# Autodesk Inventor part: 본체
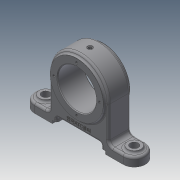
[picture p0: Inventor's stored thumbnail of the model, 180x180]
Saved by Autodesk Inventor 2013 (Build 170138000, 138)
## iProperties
Created: 2019-05
Part Number: 본체
Material: Generic
Document SubType Name: Modeling
Designer: user
Density: 1 g/cm^3
Mass: 168.533 g
Surface Area: 318.665 cm^2
Volume: 168.533 cm^3
Author: user
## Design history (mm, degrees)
sketch "스케치1"
  geometry: L1 (40, 0)-(40, -60); L2 (-40, 0)-(-40, -60); L3 (-40, -60)-(40, -60); A1 r 40 centre (0, 0) between (40, 0) and (-40, 0); 1 further point
  constraints: 6 end point, 2 point on circle, 2 tangent, 1 centre point, 1 coincident, 1 parallel
  dimensions: "d0" = 80 diameter of A1; "d2" = 60 distance of L1.start L1.end; "d3" = 60 distance of L2.start L2.end
extrude "돌출1" new body sketch "스케치1" stored distance "d4" = 30; taper "d5" = 0 deg
node "작업 평면1"
sketch "스케치2"
  geometry: L1 (60, -15)-(-60, -15); L2 (-60, 15)-(60, 15); L3 (-60, -15)-(60, -15); L4 (60, -15)-(60, 15); L5 (60, 15)-(-60, 15); L6 (-60, 15)-(-60, -15); L7 (-60, -15)-(60, 15); L8 (60, -15)-(-60, 15); L9 (-60, 15)-(-60, -15); L10 (60, 15)-(60, -15); L11 (0, 15)-(0, -15); C1 r 15 at (-60, 0); 2 further points
  constraints: 22 end point, 5 equal length, 5 midpoint, 2 horizontal, 1 centre point, 1 perpendicular, 1 symmetric about line, 1 vertical alignment, 3 other
  dimensions: "d9" = 120 distance of L2.start L2.end; "d10" = 30 distance of L1.start L2.end
extrude "돌출2" join sketch "스케치2" distance "d11" = 12; taper "d12" = 0 deg
sketch "스케치3"
  geometry: C1 r 36 at (0, 0); A1 r 40 centre (0, 0) between (40, 0) and (-40, 0) reference
  constraints: 1 centre point, 1 coincident
  dimensions: "d13" = 72 diameter of C1
extrude "돌출3" join sketch "스케치3" distance "d14" = 3; taper "d15" = 0 deg
sketch "스케치4"
  geometry: C1 r 36 at (0, 0); A1 r 40 centre (0, 0) between (40, 0) and (-40, 0) reference
  constraints: 1 centre point, 1 coincident
  dimensions: "d16" = 72 diameter of C1
extrude "돌출4" join sketch "스케치4" distance "d17" = 3; taper "d18" = 0 deg
sketch "스케치5"
  geometry: C1 r 36 at (0, 0) reference; C2 r 26 at (0, 0)
  constraints: 1 centre point, 1 coincident
  dimensions: "d19" = 52 diameter of C2
extrude "돌출5" cut sketch "스케치5" stored distance "d20" = 3; taper "d21" = 0 deg
sketch "스케치6"
  geometry: L1 (-40, 0)-(-40, -48) reference; L2 (-60, -60)-(60, -60) reference; L3 (0, -60)-(-36, -60); L4 (-36, -60)-(-36, -56); L5 (-36, -56)-(-30, -56); L6 (-30, -56)-(-30, -50); L7 (-30, -50)-(0, -50); L8 (0, -60)-(0, -50); L9 (30, -50)-(0, -50); L10 (30, -56)-(30, -50); L11 (36, -56)-(30, -56); L12 (36, -60)-(36, -56); L13 (0, -60)-(36, -60)
  constraints: 22 end point, 4 symmetric about line, 3 perpendicular, 1 midpoint, 1 parallel, 1 point on line
  dimensions: "d23" = 36 distance of L3.start L3.end; "d24" = 4 distance of L3.end L4.end; "d26" = 6 distance of L4.end L5.end; "d27" = 6 distance of L5.end L6.end; "d28" = 30 distance of L6.end L7.end
extrude "돌출6" cut sketch "스케치6" stored distance "d29" = 3; taper "d30" = 0 deg
chamfer "모따기1" distance "d31" = 1; stored, may be unused: second distance "d32" = 2, angle "d33" = 45 deg
sketch "스케치8"
  geometry: L1 (0, 27)-(0, 26); C1 r 36 at (0, 0) reference; C2 r 1.5 at (0, 26); 2 further points
  constraints: 3 vertical alignment, 2 end point, 1 centre point, 1 coincident, 1 vertical, 2 other
  dimensions: "d35" = 3 diameter of C2
extrude "돌출7" cut sketch "스케치8" stored distance "d36" = 3; taper "d37" = 0 deg
sketch "스케치9"
  geometry: L1 (0, 0)-(0, 31); C1 r 36 at (0, 0) reference; 1 further point
  constraints: 2 end point, 1 coincident, 1 vertical
  dimensions: "d38" = 31 distance of L1.start L1.end
hole "구멍1" sketch "스케치9" at (0, 31) diameter "d39" = 3.242; stored, may be unused: countersink angle "d43" = 90 deg, drill point angle "d45" = 118 deg; dims "d40" = 6, "d41" = 7, "d42" = 1, "d44" = 8
sketch "스케치10"
  geometry: L1 (60, 15)-(40, 15) reference; L2 (40, -15)-(60, -15) reference; C1 r 9 at (-60, 0); C2 r 9 at (60, 0); A1 r 15 centre (-60, 0) between (-60, 15) and (-60, -15) reference; A2 r 15 centre (60, 0) between (60, -15) and (60, 15) reference; 1 further point
  constraints: 2 centre point, 2 coincident
  dimensions: "d49" = 18 diameter of C1; "d50" = 18 diameter of C2
extrude "돌출8" join sketch "스케치10" distance "d51" = 3; taper "d52" = 0 deg
sketch "스케치11"
  geometry: C1 r 9 at (0, 0) reference; C2 r 9 at (-120, 0) reference; C3 r 5.5 at (-120, 0); C4 r 5.5 at (0, 0); 1 further point
  constraints: 2 centre point, 2 coincident
  dimensions: "d53" = 11 diameter of C3; "d54" = 11 diameter of C4
extrude "돌출9" cut sketch "스케치11" stored distance "d55" = 3; taper "d56" = 0 deg
node "작업 평면2"
sketch "스케치13"
  geometry: 2 further points
  constraints: 1 coincident
hole "구멍3" sketch "스케치13" diameter "d65" = 4.917; stored, may be unused: countersink angle "d69" = 90 deg, drill point angle "d71" = 0 deg; dims "d66" = 8, "d67" = 7, "d68" = 1, "d70" = 10
fillet "모깎기1" dims "d77" = 6
fillet "모깎기2" dims "d78" = 3
fillet "모깎기3" dims "d79" = 3
fillet "모깎기4" dims "d80" = 3
fillet "모깎기5" dims "d81" = 3
sketch "스케치18"
  geometry: L1 (-27, -50)-(27, -50) reference; C1 r 36 at (0, 0) reference; 1 further point
  constraints: 1 vertical alignment, 1 other
  dimensions: "d82" = 7 distance from line of L1 point (0, -43)
feature "엠보싱1" sketch "스케치18" dims "d0" = 80, "d2" = 60, "d3" = 60, "d83" = 0.5, "d84" = 0
fillet "모깎기6" dims "d92" = 3
fillet "모깎기7" dims "d93" = 3
sketch "스케치21"
  geometry: C1 r 2.458 at (0, 0) reference; 1 further point
  constraints: 1 coincident
hole "구멍4" sketch "스케치21" at (0, 0) diameter "d94" = 2; stored, may be unused: countersink angle "d98" = 90 deg, drill point angle "d100" = 0 deg; dims "d95" = 6, "d96" = 5, "d97" = 2, "d99" = 8
node "솔리드1"
pattern_circular "원형 패턴1" dims angle "d47" = 360 deg
mirror "대칭1"
